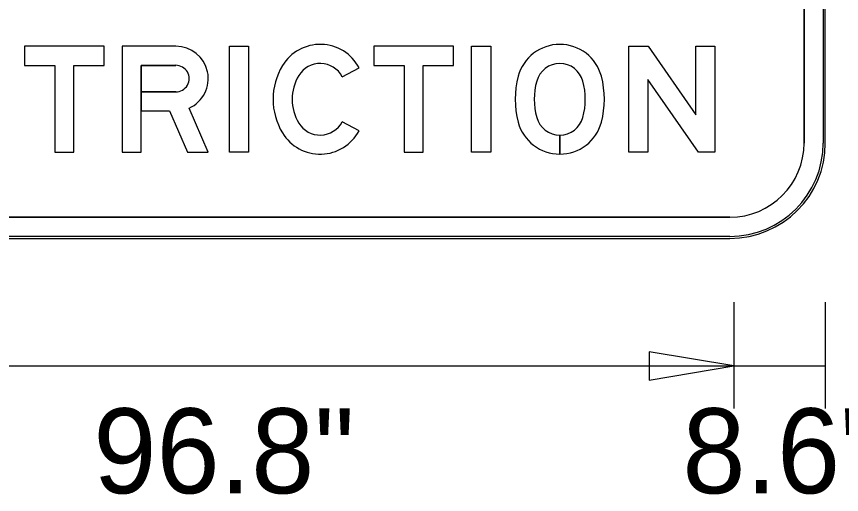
# Model space of a CAD drawing. Extents: x 17890628 to 17890844, y 17897508 to 17897992.
# Drawn here: x 17890748.8 to 17890755.28, y 17897541.58 to 17897545.33 of the extents above; entities that cross this region are included whole.
import ezdxf

# ---------------------------------------------------------------- set-up
doc = ezdxf.new("R2010")
doc.units = 0
for name, color, linetype in [('GSBWFill', 7, 'Continuous'), ('GSColorFill', 7, 'Continuous'), ('GSDims', 7, 'Continuous'), ('GSOutline', 7, 'Continuous')]:
    doc.layers.add(name, color=color, linetype=linetype)

msp = doc.modelspace()

# ---------------------------------------------------------------- linework, layer by layer
at = {"layer": 'GSBWFill'}
for p, q in [((17890754.9873, 17897548.3313), (17890754.9873, 17897544.336)), ((17890755.1541, 17897544.336), (17890755.1541, 17897548.3313)), ((17890751.3599, 17897544.8566), (17890751.4925, 17897544.927)), ((17890751.4925, 17897544.4318), (17890751.3599, 17897544.5022)), ((17890751.3599, 17897544.5022), (17890751.3599, 17897544.5022)), ((17890753.0689, 17897544.2486), (17890753.0689, 17897544.3985)), ((17890753.0689, 17897544.3985), (17890753.0689, 17897544.2486)), ((17890754.4034, 17897543.7534), (17890746.3979, 17897543.7534)), ((17890746.3979, 17897543.5869), (17890754.4034, 17897543.5869))]:
    msp.add_line(p, q, dxfattribs=at)
for points in [[(17890748.8651, 17897544.9457), (17890749.1028, 17897544.9457), (17890749.1028, 17897544.2632), (17890749.253, 17897544.2632), (17890749.253, 17897544.9457), (17890749.4907, 17897544.9457), (17890749.4907, 17897545.0956), (17890748.8651, 17897545.0956)], [(17890750.4749, 17897544.2632), (17890750.4749, 17897545.0956), (17890750.625, 17897545.0956), (17890750.625, 17897544.2632)], [(17890751.6092, 17897544.9457), (17890751.847, 17897544.9457), (17890751.847, 17897544.2632), (17890751.9971, 17897544.2632), (17890751.9971, 17897544.9457), (17890752.2348, 17897544.9457), (17890752.2348, 17897545.0956), (17890751.6092, 17897545.0956)], [(17890752.3766, 17897544.2632), (17890752.3766, 17897545.0956), (17890752.5267, 17897545.0956), (17890752.5267, 17897544.2632)], [(17890754.2866, 17897545.0956), (17890754.2866, 17897544.2632), (17890754.1574, 17897544.2632), (17890753.7612, 17897544.8334), (17890753.7612, 17897544.2632), (17890753.611, 17897544.2632), (17890753.611, 17897545.0956), (17890753.7617, 17897545.0956), (17890754.1365, 17897544.5561), (17890754.1365, 17897545.0956)]]:
    msp.add_lwpolyline(points, close=True, dxfattribs=at)
for points in [[(17890750.0537, 17897545.0956), (17890749.6325, 17897545.0956), (17890749.6325, 17897544.2632), (17890749.7826, 17897544.2632), (17890749.7826, 17897544.9457), (17890750.0537, 17897544.9457)], [(17890750.0537, 17897544.7376), (17890749.7826, 17897544.7376), (17890749.7826, 17897544.5878)], [(17890749.7826, 17897544.5878), (17890750.0036, 17897544.5878), (17890750.1445, 17897544.2632), (17890750.3081, 17897544.2632), (17890750.1576, 17897544.61)]]:
    msp.add_lwpolyline(points, dxfattribs=at)
for centre, major_axis, ratio, start_param, end_param in [((17890750.0537, 17897544.8417), (0.2544, 0), 0.997926, 5.1333, 7.853982), ((17890751.1869, 17897544.7647), (0.3461, 0), 0.997927, 0.489154, 2.596176), ((17890753.0689, 17897544.7728), (0.338, 0), 0.997924, 0.261132, 2.88046), ((17890750.0537, 17897544.8417), (0.1043, 0), 0.997926, 4.712389, 7.853982), ((17890751.3278, 17897544.6794), (0.5109, 0), 0.997927, 2.596176, 3.68701), ((17890751.1869, 17897544.7647), (0.196, 0), 0.997927, 0.489154, 2.596176), ((17890753.0689, 17897544.7728), (0.1879, 0), 0.997924, 0.261132, 2.88046), ((17890751.3278, 17897544.6794), (0.3608, 0), 0.997927, 2.596176, 3.68701), ((17890753.4192, 17897544.6794), (0.7006, 0), 0.997924, 2.88046, 3.402725), ((17890753.4192, 17897544.6794), (0.5505, 0), 0.997924, 2.88046, 3.402725), ((17890752.7186, 17897544.6794), (0.5505, 0), 0.997924, 6.022053, 6.544317), ((17890752.7186, 17897544.6794), (0.7006, 0), 0.997924, 6.022053, 6.544317), ((17890751.1869, 17897544.5941), (0.196, 0), 0.997927, 3.68701, 5.794031), ((17890753.0689, 17897544.586), (0.338, 0), 0.997924, 3.402725, 4.712389), ((17890753.0689, 17897544.586), (0.1879, 0), 0.997924, 3.402725, 4.712389), ((17890753.0689, 17897544.586), (0.1879, 0), 0.997924, 4.712611, 6.022053), ((17890753.0689, 17897544.586), (0.338, 0), 0.997924, 4.712512, 6.022053), ((17890751.1869, 17897544.5941), (0.3461, 0), 0.997927, 3.68701, 5.794031), ((17890754.4034, 17897544.336), (0.7507, 0), 0.997922, 4.712389, 6.283185), ((17890754.4034, 17897544.336), (0.5839, 0), 0.997922, 4.712389, 6.283185)]:
    msp.add_ellipse(centre, major_axis=major_axis, ratio=ratio, start_param=start_param, end_param=end_param, dxfattribs=at)
at = {"layer": 'GSColorFill'}
for p, q in [((17890754.9873, 17897548.3313), (17890754.9873, 17897544.336)), ((17890755.1374, 17897548.3313), (17890755.1374, 17897544.336)), ((17890755.1541, 17897544.336), (17890755.1541, 17897548.3313)), ((17890755.1541, 17897544.336), (17890755.1541, 17897548.3313)), ((17890755.1541, 17897544.336), (17890755.1541, 17897547.0204)), ((17890751.3599, 17897544.8566), (17890751.4925, 17897544.927)), ((17890751.4925, 17897544.4318), (17890751.3599, 17897544.5022)), ((17890751.3599, 17897544.5022), (17890751.3599, 17897544.5022)), ((17890753.0689, 17897544.2486), (17890753.0689, 17897544.3985)), ((17890753.0689, 17897544.3985), (17890753.0689, 17897544.2486)), ((17890754.4034, 17897543.7534), (17890746.3979, 17897543.7534)), ((17890746.3962, 17897543.5869), (17890754.4034, 17897543.5869)), ((17890754.4034, 17897543.6036), (17890746.3964, 17897543.6036)), ((17890746.3964, 17897543.5869), (17890754.4034, 17897543.5869)), ((17890746.3979, 17897543.5869), (17890754.4034, 17897543.5869))]:
    msp.add_line(p, q, dxfattribs=at)
for points in [[(17890748.8651, 17897544.9457), (17890749.1028, 17897544.9457), (17890749.1028, 17897544.2632), (17890749.253, 17897544.2632), (17890749.253, 17897544.9457), (17890749.4907, 17897544.9457), (17890749.4907, 17897545.0956), (17890748.8651, 17897545.0956)], [(17890750.4749, 17897544.2632), (17890750.4749, 17897545.0956), (17890750.625, 17897545.0956), (17890750.625, 17897544.2632)], [(17890751.6092, 17897544.9457), (17890751.847, 17897544.9457), (17890751.847, 17897544.2632), (17890751.9971, 17897544.2632), (17890751.9971, 17897544.9457), (17890752.2348, 17897544.9457), (17890752.2348, 17897545.0956), (17890751.6092, 17897545.0956)], [(17890752.3766, 17897544.2632), (17890752.3766, 17897545.0956), (17890752.5267, 17897545.0956), (17890752.5267, 17897544.2632)], [(17890754.2866, 17897545.0956), (17890754.2866, 17897544.2632), (17890754.1574, 17897544.2632), (17890753.7612, 17897544.8334), (17890753.7612, 17897544.2632), (17890753.611, 17897544.2632), (17890753.611, 17897545.0956), (17890753.7617, 17897545.0956), (17890754.1365, 17897544.5561), (17890754.1365, 17897545.0956)]]:
    msp.add_lwpolyline(points, close=True, dxfattribs=at)
for points in [[(17890750.0537, 17897545.0956), (17890749.6325, 17897545.0956), (17890749.6325, 17897544.2632), (17890749.7826, 17897544.2632), (17890749.7826, 17897544.9457), (17890750.0537, 17897544.9457)], [(17890750.0537, 17897544.7376), (17890749.7826, 17897544.7376), (17890749.7826, 17897544.5878)], [(17890749.7826, 17897544.5878), (17890750.0036, 17897544.5878), (17890750.1445, 17897544.2632), (17890750.3081, 17897544.2632), (17890750.1576, 17897544.61)]]:
    msp.add_lwpolyline(points, dxfattribs=at)
for centre, major_axis, ratio, start_param, end_param in [((17890750.0537, 17897544.8417), (0.2544, 0), 0.997926, 5.1333, 7.853982), ((17890751.1869, 17897544.7647), (0.3461, 0), 0.997927, 0.489154, 2.596176), ((17890753.0689, 17897544.7728), (0.338, 0), 0.997924, 0.261132, 2.88046), ((17890750.0537, 17897544.8417), (0.1043, 0), 0.997926, 4.712389, 7.853982), ((17890751.3278, 17897544.6794), (0.5109, 0), 0.997927, 2.596176, 3.68701), ((17890751.1869, 17897544.7647), (0.196, 0), 0.997927, 0.489154, 2.596176), ((17890753.0689, 17897544.7728), (0.1879, 0), 0.997924, 0.261132, 2.88046), ((17890751.3278, 17897544.6794), (0.3608, 0), 0.997927, 2.596176, 3.68701), ((17890753.4192, 17897544.6794), (0.7006, 0), 0.997924, 2.88046, 3.402725), ((17890753.4192, 17897544.6794), (0.5505, 0), 0.997924, 2.88046, 3.402725), ((17890752.7186, 17897544.6794), (0.5505, 0), 0.997924, 6.022053, 6.544317), ((17890752.7186, 17897544.6794), (0.7006, 0), 0.997924, 6.022053, 6.544317), ((17890751.1869, 17897544.5941), (0.196, 0), 0.997927, 3.68701, 5.794031), ((17890753.0689, 17897544.586), (0.338, 0), 0.997924, 3.402725, 4.712389), ((17890753.0689, 17897544.586), (0.1879, 0), 0.997924, 3.402725, 4.712389), ((17890753.0689, 17897544.586), (0.1879, 0), 0.997924, 4.712611, 6.022053), ((17890753.0689, 17897544.586), (0.338, 0), 0.997924, 4.712512, 6.022053), ((17890751.1869, 17897544.5941), (0.3461, 0), 0.997927, 3.68701, 5.794031), ((17890754.4034, 17897544.336), (0.7507, 0), 0.997922, 4.712389, 6.283185), ((17890754.4034, 17897544.336), (0.7507, 0), 0.997922, 4.712389, 6.283185), ((17890754.4034, 17897544.336), (0.5839, 0), 0.997922, 4.712389, 6.283185), ((17890754.4034, 17897544.336), (0.7507, 0), 0.997922, 4.712389, 6.283185), ((17890754.4034, 17897544.336), (0.734, 0), 0.997922, 4.712389, 6.283185)]:
    msp.add_ellipse(centre, major_axis=major_axis, ratio=ratio, start_param=start_param, end_param=end_param, dxfattribs=at)
at = {"layer": 'GSDims'}
for p, q in [((17890754.4368, 17897543.0869), (17890754.4368, 17897542.2536)), ((17890754.4368, 17897543.0869), (17890754.4368, 17897542.2536)), ((17890755.1541, 17897543.0869), (17890755.1541, 17897542.2536)), ((17890746.3629, 17897542.5869), (17890754.4368, 17897542.5869)), ((17890754.4368, 17897542.5869), (17890755.1541, 17897542.5869))]:
    msp.add_line(p, q, dxfattribs=at)
msp.add_lwpolyline([(17890754.4368, 17897542.5869), (17890753.7701, 17897542.698), (17890753.7701, 17897542.4758)], close=True, dxfattribs=at)
at = {"layer": 'GSOutline'}
for p, q in [((17890754.9873, 17897544.336), (17890754.9873, 17897548.3313)), ((17890755.1541, 17897544.336), (17890755.1541, 17897548.3313)), ((17890751.3599, 17897544.8566), (17890751.4925, 17897544.927)), ((17890749.7826, 17897544.7376), (17890750.0537, 17897544.7376)), ((17890751.4925, 17897544.4318), (17890751.3599, 17897544.5022)), ((17890751.3599, 17897544.5022), (17890751.3599, 17897544.5022)), ((17890746.3962, 17897543.7534), (17890754.4034, 17897543.7534)), ((17890746.3962, 17897543.5869), (17890754.4034, 17897543.5869))]:
    msp.add_line(p, q, dxfattribs=at)
for points in [[(17890748.8651, 17897544.9457), (17890749.1028, 17897544.9457), (17890749.1028, 17897544.2632), (17890749.253, 17897544.2632), (17890749.253, 17897544.9457), (17890749.4907, 17897544.9457), (17890749.4907, 17897545.0956), (17890748.8651, 17897545.0956)], [(17890750.4749, 17897544.2632), (17890750.4749, 17897545.0956), (17890750.625, 17897545.0956), (17890750.625, 17897544.2632)], [(17890751.6092, 17897544.9457), (17890751.847, 17897544.9457), (17890751.847, 17897544.2632), (17890751.9971, 17897544.2632), (17890751.9971, 17897544.9457), (17890752.2348, 17897544.9457), (17890752.2348, 17897545.0956), (17890751.6092, 17897545.0956)], [(17890752.3766, 17897544.2632), (17890752.3766, 17897545.0956), (17890752.5267, 17897545.0956), (17890752.5267, 17897544.2632)], [(17890754.2866, 17897545.0956), (17890754.2866, 17897544.2632), (17890754.1574, 17897544.2632), (17890753.7612, 17897544.8334), (17890753.7612, 17897544.2632), (17890753.611, 17897544.2632), (17890753.611, 17897545.0956), (17890753.7617, 17897545.0956), (17890754.1365, 17897544.5561), (17890754.1365, 17897545.0956)]]:
    msp.add_lwpolyline(points, close=True, dxfattribs=at)
for points in [[(17890750.0537, 17897545.0956), (17890749.6325, 17897545.0956), (17890749.6325, 17897544.2632), (17890749.7826, 17897544.2632), (17890749.7826, 17897544.5878), (17890750.0036, 17897544.5878)], [(17890750.0537, 17897544.9457), (17890749.7826, 17897544.9457), (17890749.7826, 17897544.7376)], [(17890750.0036, 17897544.5878), (17890750.1445, 17897544.2632), (17890750.3081, 17897544.2632), (17890750.1576, 17897544.61)]]:
    msp.add_lwpolyline(points, dxfattribs=at)
for centre, major_axis, ratio, start_param, end_param in [((17890750.0537, 17897544.8417), (0.2544, 0), 0.997926, 5.1333, 7.853982), ((17890751.1869, 17897544.7647), (0.3461, 0), 0.997927, 0.489154, 2.596176), ((17890753.0689, 17897544.7728), (0.338, 0), 0.997924, 0.261132, 2.88046), ((17890750.0537, 17897544.8417), (0.1043, 0), 0.997926, 4.712389, 7.853982), ((17890751.3278, 17897544.6794), (0.5109, 0), 0.997927, 2.596176, 3.68701), ((17890751.1869, 17897544.7647), (0.196, 0), 0.997927, 0.489154, 2.596176), ((17890753.0689, 17897544.7728), (0.1879, 0), 0.997924, 0.261132, 2.88046), ((17890751.3278, 17897544.6794), (0.3608, 0), 0.997927, 2.596176, 3.68701), ((17890753.4192, 17897544.6794), (0.7006, 0), 0.997924, 2.88046, 3.402725), ((17890753.4192, 17897544.6794), (0.5505, 0), 0.997924, 2.88046, 3.402725), ((17890752.7186, 17897544.6794), (0.5505, 0), 0.997924, 6.022053, 6.544317), ((17890752.7186, 17897544.6794), (0.7006, 0), 0.997924, 6.022053, 6.544317), ((17890751.1869, 17897544.5941), (0.196, 0), 0.997927, 3.68701, 5.794031), ((17890753.0689, 17897544.586), (0.338, 0), 0.997924, 3.402725, 6.022053), ((17890753.0689, 17897544.586), (0.1879, 0), 0.997924, 3.402725, 6.022053), ((17890751.1869, 17897544.5941), (0.3461, 0), 0.997927, 3.68701, 5.794031), ((17890754.4034, 17897544.336), (0.7507, 0), 0.997922, 4.712389, 6.283185), ((17890754.4034, 17897544.336), (0.5839, 0), 0.997922, 4.712389, 6.283185)]:
    msp.add_ellipse(centre, major_axis=major_axis, ratio=ratio, start_param=start_param, end_param=end_param, dxfattribs=at)

# ---------------------------------------------------------------- texts
at = {"layer": 'GSDims'}
for s, p in [('96.8"', (17890749.4061, 17897541.5869)), ('8.6"', (17890754.0313, 17897541.5869))]:
    msp.add_text(s, height=0.66667, dxfattribs=at).set_placement(p)

doc.saveas('drawing.dxf')
